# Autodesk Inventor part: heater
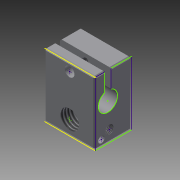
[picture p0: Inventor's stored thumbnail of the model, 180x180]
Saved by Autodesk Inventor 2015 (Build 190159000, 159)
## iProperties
Created: 2015-02
Part Number: heater
Material: Типовые
Document SubType Name: Modeling
Designer: Parabolik
Density: 1 g/cm^3
Appearance: По умолчанию
Author: Parabolik
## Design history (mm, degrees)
sketch "Эскиз1"
  geometry: L1 (0, -20)-(0, 0); L2 (5, 0)-(5, -5.645); L3 (11.5, 0)-(11.5, -20); L4 (11.5, -20)-(0, -20); L5 (3, -5.645)-(3, 0); L6 (3, 0)-(0, 0); L7 (11.5, 0)-(5, 0); A1 r 3.025 centre (4, -8.5) between (3, -5.645) and (5, -5.645); 1 further point
  constraints: 14 end point, 2 horizontal, 2 point on circle, 2 vertical, 1 centre point, 1 coincident, 1 perpendicular
  dimensions: "d4" = 3.025 radius of A1; "d6" = 11.5 distance between parallel lines of L1 L3; "d8" = 20 distance between parallel lines of L7 L4; "d9" = 6.5 distance between parallel lines of L2 L3; "d10" = 8.5 distance from line of L7 A1.centre; "d11" = 4 distance from line of L1 A1.centre
extrude "Выдавливание1" new body sketch "Эскиз1" distance "d12" = 16; taper "d13" = 0 deg
sketch "Эскиз2"
  geometry: L1 (20, 0)-(0, 0) reference; L2 (20, 11.5)-(20, 0) reference; 4 further points
  constraints: 2 coincident
  dimensions: "d16" = 2 distance from line of point (18, 2) L1; "d17" = 2 distance from line of point (18, 2) L2; "d18" = 3.5 distance from line of L2 point (16.5, 4.5); "d19" = 4.5 distance from line of point (16.5, 4.5) L1
hole "Отверстие1" sketch "Эскиз2" diameter "d24" = 2.621; stored, may be unused: countersink angle "d28" = 82 deg, drill point angle "d30" = 118 deg; dims "d25" = 6, "d26" = 3.023, "d27" = 2, "d29" = 4
hole "Отверстие3" sketch "Эскиз2" diameter "d52" = 1.2; stored, may be unused: countersink angle "d56" = 90 deg, drill point angle "d58" = 118 deg; dims "d53" = 6, "d54" = 4, "d55" = 2, "d57" = 4.5
hole "Отверстие4" sketch "Эскиз2" diameter "d59" = 2; stored, may be unused: countersink angle "d63" = 90 deg, drill point angle "d65" = 118 deg; dims "d60" = 6, "d61" = 4, "d62" = 2, "d64" = 2
sketch "Эскиз3"
  geometry: L1 (0, 0)-(0, 20) reference; L2 (0, 0)-(-16, 0) reference; L3 (0, 20)-(-16, 20) reference; 3 further points
  constraints: 1 coincident
  dimensions: "d32" = 8 distance from line of point (-8, 17.5) L1; "d34" = 2.5 distance from line of point (-8, 17.5) L3
hole "Отверстие2" sketch "Эскиз3" diameter "d38" = 2.621; stored, may be unused: countersink angle "d42" = 82 deg, drill point angle "d44" = 0 deg; dims "d39" = 11.5, "d40" = 3.023, "d41" = 5, "d43" = 11.5
chamfer "Фаска1" distance "d47" = 0.5; stored, may be unused: second distance "d48" = 2, angle "d49" = 45 deg
hole "Отверстие5" sketch "Эскиз3" diameter "d100" = 5.917; stored, may be unused: countersink angle "d104" = 90 deg, drill point angle "d106" = 118 deg; dims "d101" = 14, "d102" = 4, "d103" = 2, "d105" = 19.1
node "Твердое тело1"
